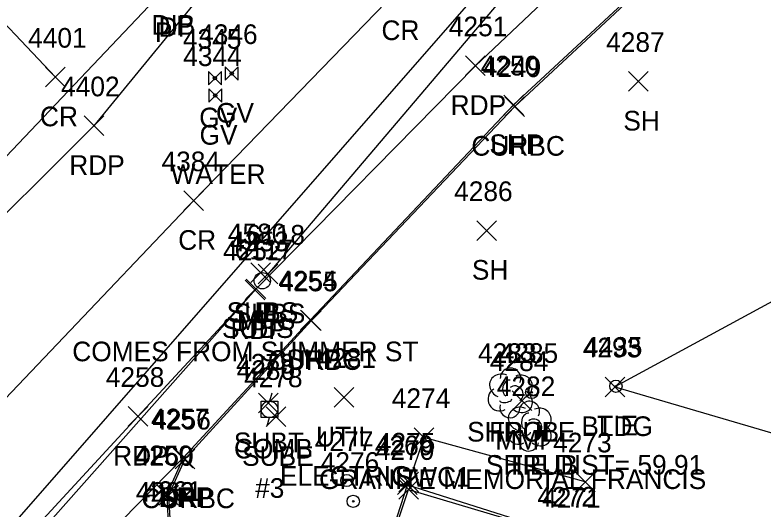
# Model space of a CAD drawing. Extents: x 1653135 to 1655489, y 602711 to 605684.
# Drawn here: x 1653342.1 to 1653418.2, y 604982.6 to 605032.9 of the extents above; entities that cross this region are included whole.
import ezdxf

# ---------------------------------------------------------------- set-up
doc = ezdxf.new("R2010")
doc.units = 0
for name, color, linetype in [('C_A', 7, 'Continuous'), ('C_C', 7, 'Continuous'), ('C_I', 7, 'Continuous'), ('CBP', 7, 'Continuous'), ('D_A', 7, 'Continuous'), ('D_I', 7, 'Continuous'), ('D_TIC', 7, 'Continuous'), ('DCP', 7, 'Continuous'), ('L_A', 7, 'Continuous'), ('L_C', 7, 'Continuous'), ('L_I', 7, 'Continuous'), ('L_TIC', 7, 'Continuous'), ('LBC', 7, 'Continuous'), ('LFP', 7, 'Continuous'), ('LSH', 7, 'Continuous'), ('P_A', 7, 'Continuous'), ('P_I', 7, 'Continuous'), ('P_TIC', 7, 'Continuous'), ('PET', 7, 'Continuous'), ('PRC', 7, 'Continuous'), ('PSP', 7, 'Continuous'), ('R_A', 7, 'Continuous'), ('R_I', 7, 'Continuous'), ('R_TIC', 7, 'Continuous'), ('RC', 7, 'Continuous'), ('RDP', 7, 'Continuous'), ('RSW', 7, 'Continuous'), ('U_A', 7, 'Continuous'), ('U_C', 7, 'Continuous'), ('U_I', 7, 'Continuous'), ('U_TIC', 7, 'Continuous'), ('UDEFAULT', 7, 'Continuous'), ('UP', 7, 'Continuous'), ('UPGW', 7, 'Continuous'), ('USA', 7, 'Continuous'), ('USMH', 7, 'Continuous'), ('UWV', 7, 'Continuous')]:
    doc.layers.add(name, color=color, linetype=linetype)

msp = doc.modelspace()

# ---------------------------------------------------------------- linework, layer by layer
at = {"layer": 'CBP'}
for radius in [0.625, 0.0833]:
    msp.add_circle((1653403.206, 604995.09), radius, dxfattribs=at)
at = {"layer": 'D_TIC'}
for points in [[(1653366.082, 605005.63), (1653368.082, 605007.63)], [(1653368.082, 605005.63), (1653366.082, 605007.63)], [(1653366.8, 605005.5), (1653368.8, 605007.5)], [(1653368.8, 605005.5), (1653366.8, 605007.5)], [(1653365.6, 605004), (1653367.6, 605006)], [(1653367.6, 605004), (1653365.6, 605006)]]:
    msp.add_lwpolyline(points, dxfattribs=at)
at = {"layer": 'DCP'}
for points in [[(1653257.187, 604884.19), (1653422.369, 605073.113)], [(1653334.204, 605011.132), (1653356.94, 605035.103)]]:
    msp.add_lwpolyline(points, dxfattribs=at)
at = {"layer": 'L_TIC'}
for points in [[(1653404.468, 605025.109), (1653406.468, 605027.109)], [(1653406.468, 605025.109), (1653404.468, 605027.109)], [(1653404.468, 605025.109), (1653406.468, 605027.109)], [(1653406.468, 605025.109), (1653404.468, 605027.109)], [(1653389.063, 605009.932), (1653391.063, 605011.932)], [(1653391.063, 605009.932), (1653389.063, 605011.932)], [(1653389.063, 605009.932), (1653391.063, 605011.932)], [(1653391.063, 605009.932), (1653389.063, 605011.932)], [(1653402.096, 604994.024), (1653404.096, 604996.024)], [(1653404.096, 604994.024), (1653402.096, 604996.024)], [(1653402.096, 604994.024), (1653404.096, 604996.024)], [(1653404.096, 604994.024), (1653402.096, 604996.024)], [(1653392.641, 604992.631), (1653394.641, 604994.631)], [(1653394.641, 604992.631), (1653392.641, 604994.631)], [(1653392.641, 604992.631), (1653394.641, 604994.631)], [(1653394.641, 604992.631), (1653392.641, 604994.631)]]:
    msp.add_lwpolyline(points, dxfattribs=at)
at = {"layer": 'LBC'}
msp.add_lwpolyline([(1653550.972, 604997.314), (1653536.605, 605023.768), (1653518.373, 605057.282), (1653491.861, 605043.128), (1653464.288, 605028.284), (1653448.833, 605019.935), (1653427.545, 605008.288), (1653403.096, 604995.024), (1653422.273, 604989.413)], dxfattribs=at)
at = {"layer": 'LFP'}
for radius in [0.625, 0.0833]:
    msp.add_circle((1653394.638, 604994.466), radius, dxfattribs=at)
at = {"layer": 'LSH'}
for p, q in [((1653392.438, 604994.459), (1653392.438, 604994.459)), ((1653392.438, 604994.459), (1653392.438, 604994.459)), ((1653394.345, 604991.082), (1653394.345, 604991.082)), ((1653394.345, 604991.082), (1653394.345, 604991.082))]:
    msp.add_line(p, q, dxfattribs=at)
for centre in [(1653392.485, 604995.893), (1653394.392, 604992.516)]:
    msp.add_arc(centre, 1.047, 335.52715, 180.95627, dxfattribs=at)
for centre, major_axis, ratio, start_param, end_param in [((1653391.646, 604995.126), (1.21, -0.512), 0.895232, 1.570796, 4.712389), ((1653393.479, 604995.043), (-1.141, -0.483), 0.949671, 1.570796, 4.712389), ((1653392.229, 604994.917), (-0.208, -0.792), 0.645439, 3.141593, 6.283185), ((1653392.938, 604994.292), (-0.5, 0.667), 0.989748, 3.141593, 6.283185), ((1653391.355, 604993.751), (0.584, -1.042), 0.959034, 3.141593, 6.283185), ((1653393.438, 604993.626), (-1.09, 0.792), 0.841452, 1.570796, 4.712389), ((1653391.98, 604993.709), (-0.625, -0.083), 0.423636, 0, 3.141593), ((1653392.438, 604992.959), (0.265, 1.061), 0.942809, 1.570796, 4.712389), ((1653393.553, 604991.749), (1.21, -0.512), 0.895232, 1.570796, 4.712389), ((1653395.387, 604991.666), (-1.141, -0.483), 0.949671, 1.570796, 4.712389), ((1653394.137, 604991.541), (-0.208, -0.792), 0.645439, 3.141593, 6.283185), ((1653393.262, 604990.374), (0.584, -1.042), 0.959034, 3.141593, 6.283185), ((1653394.845, 604990.916), (-0.5, 0.667), 0.989748, 3.141593, 6.283185), ((1653395.345, 604990.249), (-1.09, 0.792), 0.841452, 1.570796, 4.712389), ((1653394.345, 604989.582), (0.265, 1.061), 0.942809, 1.570796, 4.712389), ((1653393.887, 604990.332), (-0.625, -0.083), 0.423636, 0, 3.141593)]:
    msp.add_ellipse(centre, major_axis=major_axis, ratio=ratio, start_param=start_param, end_param=end_param, dxfattribs=at)
at = {"layer": 'P_TIC'}
for points in [[(1653387.905, 605026.698), (1653389.905, 605028.698)], [(1653389.905, 605026.698), (1653387.905, 605028.698)], [(1653387.905, 605026.698), (1653389.905, 605028.698)], [(1653389.905, 605026.698), (1653387.905, 605028.698)], [(1653345.194, 605025.541), (1653347.194, 605027.541)], [(1653347.194, 605025.541), (1653345.194, 605027.541)], [(1653345.194, 605025.541), (1653347.194, 605027.541)], [(1653347.194, 605025.541), (1653345.194, 605027.541)], [(1653391.797, 605022.713), (1653393.797, 605024.713)], [(1653393.797, 605022.713), (1653391.797, 605024.713)], [(1653391.797, 605022.713), (1653393.797, 605024.713)], [(1653393.797, 605022.713), (1653391.797, 605024.713)], [(1653349.113, 605020.59), (1653351.113, 605022.59)], [(1653351.113, 605020.59), (1653349.113, 605022.59)], [(1653349.113, 605020.59), (1653351.113, 605022.59)], [(1653351.113, 605020.59), (1653349.113, 605022.59)], [(1653359.25, 605012.969), (1653361.25, 605014.969)], [(1653361.25, 605012.969), (1653359.25, 605014.969)], [(1653359.25, 605012.969), (1653361.25, 605014.969)], [(1653361.25, 605012.969), (1653359.25, 605014.969)], [(1653365.499, 605003.888), (1653367.499, 605005.888)], [(1653367.499, 605003.888), (1653365.499, 605005.888)], [(1653365.499, 605003.888), (1653367.499, 605005.888)], [(1653367.499, 605003.888), (1653365.499, 605005.888)], [(1653371.132, 605000.835), (1653373.132, 605002.835)], [(1653373.132, 605000.835), (1653371.132, 605002.835)], [(1653371.132, 605000.835), (1653373.132, 605002.835)], [(1653373.132, 605000.835), (1653371.132, 605002.835)], [(1653353.584, 604991.023), (1653355.584, 604993.023)], [(1653355.584, 604991.023), (1653353.584, 604993.023)], [(1653353.584, 604991.023), (1653355.584, 604993.023)], [(1653355.584, 604991.023), (1653353.584, 604993.023)], [(1653358.179, 604986.803), (1653360.179, 604988.803)], [(1653360.179, 604986.803), (1653358.179, 604988.803)], [(1653358.179, 604986.803), (1653360.179, 604988.803)], [(1653360.179, 604986.803), (1653358.179, 604988.803)]]:
    msp.add_lwpolyline(points, dxfattribs=at)
at = {"layer": 'PET'}
for points in [[(1653570.485, 605162.786), (1653545.403, 605152.188), (1653524.597, 605144.335), (1653501.66, 605134.239), (1653492.53, 605129.6), (1653483.217, 605126.16), (1653461.507, 605114.196), (1653431.751, 605097.051), (1653402.439, 605074.196), (1653383.496, 605058.488), (1653369.863, 605045.734), (1653350.113, 605021.59), (1653336.009, 605007.549), (1653322.852, 604993.824), (1653302.166, 604970.774), (1653290.93, 604958.375), (1653272.167, 604938.098), (1653250.651, 604913.142), (1653232.406, 604892.896), (1653208.357, 604866.317), (1653177.81, 604831.245), (1653160.535, 604811.983)], [(1653576.316, 605135.262), (1653553.767, 605126.837), (1653519.051, 605112.425), (1653493.535, 605100.339), (1653468.833, 605088.005), (1653447.853, 605075.02), (1653427.596, 605061.865), (1653406.781, 605044.605), (1653388.905, 605027.698), (1653366.499, 605004.888), (1653354.584, 604992.023), (1653334.896, 604970.66), (1653318.046, 604952.193), (1653296.488, 604928.187), (1653274.624, 604903.556), (1653244.239, 604868.756), (1653225.75, 604847.701), (1653206.334, 604825.65), (1653179.645, 604794.747)]]:
    msp.add_lwpolyline(points, dxfattribs=at)
at = {"layer": 'PRC'}
for points in [[(1653576.361, 605149.524), (1653550.317, 605139.021), (1653518.724, 605125.668), (1653498.017, 605116.666), (1653468.035, 605101.489), (1653440.124, 605084.852), (1653411.973, 605063.454), (1653392.179, 605045.924), (1653380.925, 605035.31), (1653360.25, 605013.969), (1653332.49, 604984.793), (1653311.146, 604961.542), (1653300.12, 604949.228), (1653281.614, 604928.677), (1653260.957, 604905.277), (1653242.089, 604884.435), (1653216.566, 604855.116), (1653187.493, 604822.135), (1653170.081, 604802.31)], [(1653325.383, 605048.447), (1653337.388, 605035.857), (1653346.194, 605026.541)]]:
    msp.add_lwpolyline(points, dxfattribs=at)
at = {"layer": 'PSP'}
msp.add_lwpolyline([(1653577.495, 605132.222), (1653555.735, 605120.61), (1653541.776, 605115.966), (1653532.613, 605114.781), (1653532.247, 605110.88), (1653522.733, 605106.898), (1653507.697, 605103.522), (1653493.111, 605096.605), (1653471.403, 605083.027), (1653450.958, 605070.25), (1653430.837, 605057.523), (1653410.321, 605040.006), (1653392.797, 605023.713), (1653372.132, 605001.835), (1653359.179, 604987.803), (1653339.003, 604967.206), (1653322.133, 604948.589), (1653300.744, 604925.192), (1653278.521, 604900.611), (1653247.528, 604865.908), (1653229.566, 604844.432), (1653209.3, 604822.581), (1653182.433, 604791.771)], dxfattribs=at)
at = {"layer": 'R_TIC'}
for points in [[(1653391.919, 605022.548), (1653393.919, 605024.548)], [(1653393.919, 605022.548), (1653391.919, 605024.548)], [(1653391.919, 605022.548), (1653393.919, 605024.548)], [(1653393.919, 605022.548), (1653391.919, 605024.548)], [(1653371.22, 605000.751), (1653373.22, 605002.751)], [(1653373.22, 605000.751), (1653371.22, 605002.751)], [(1653371.22, 605000.751), (1653373.22, 605002.751)], [(1653373.22, 605000.751), (1653371.22, 605002.751)], [(1653382.67, 604988.871), (1653384.67, 604990.871)], [(1653384.67, 604988.871), (1653382.67, 604990.871)], [(1653382.67, 604988.871), (1653384.67, 604990.871)], [(1653384.67, 604988.871), (1653382.67, 604990.871)], [(1653358.179, 604986.803), (1653360.179, 604988.803)], [(1653360.179, 604986.803), (1653358.179, 604988.803)], [(1653358.179, 604986.803), (1653360.179, 604988.803)], [(1653360.179, 604986.803), (1653358.179, 604988.803)], [(1653358.36, 604986.685), (1653360.36, 604988.685)], [(1653360.36, 604986.685), (1653358.36, 604988.685)], [(1653358.36, 604986.685), (1653360.36, 604988.685)], [(1653360.36, 604986.685), (1653358.36, 604988.685)], [(1653380.999, 604984.069), (1653382.999, 604986.069)], [(1653382.999, 604984.069), (1653380.999, 604986.069)], [(1653380.999, 604984.069), (1653382.999, 604986.069)], [(1653382.999, 604984.069), (1653380.999, 604986.069)], [(1653381.14, 604984.345), (1653383.14, 604986.345)], [(1653383.14, 604984.345), (1653381.14, 604986.345)], [(1653381.14, 604984.345), (1653383.14, 604986.345)], [(1653383.14, 604984.345), (1653381.14, 604986.345)], [(1653399.078, 604984.359), (1653401.078, 604986.359)], [(1653401.078, 604984.359), (1653399.078, 604986.359)], [(1653399.078, 604984.359), (1653401.078, 604986.359)], [(1653401.078, 604984.359), (1653399.078, 604986.359)], [(1653381.123, 604983.594), (1653383.123, 604985.594)], [(1653383.123, 604983.594), (1653381.123, 604985.594)], [(1653381.123, 604983.594), (1653383.123, 604985.594)], [(1653383.123, 604983.594), (1653381.123, 604985.594)], [(1653356.514, 604983.058), (1653358.514, 604985.058)], [(1653358.514, 604983.058), (1653356.514, 604985.058)], [(1653356.514, 604983.058), (1653358.514, 604985.058)], [(1653358.514, 604983.058), (1653356.514, 604985.058)], [(1653356.701, 604982.998), (1653358.701, 604984.998)], [(1653358.701, 604982.998), (1653356.701, 604984.998)], [(1653356.701, 604982.998), (1653358.701, 604984.998)], [(1653358.701, 604982.998), (1653356.701, 604984.998)]]:
    msp.add_lwpolyline(points, dxfattribs=at)
at = {"layer": 'RC'}
msp.add_lwpolyline([(1653461.112, 605032.534), (1653449.922, 605049.198), (1653443.907, 605057.821), (1653441.507, 605059.753), (1653437.992, 605060.258), (1653434.799, 605059.429), (1653430.986, 605057.43), (1653410.367, 605039.832), (1653392.919, 605023.548), (1653372.22, 605001.751), (1653359.36, 604987.685), (1653357.701, 604983.998), (1653357.899, 604980.417), (1653359.903, 604976.693), (1653362.858, 604974.486), (1653377.178, 604970.134), (1653381.999, 604985.069), (1653398.467, 604979.845)], dxfattribs=at)
at = {"layer": 'RDP'}
msp.add_lwpolyline([(1653359.179, 604987.803), (1653357.514, 604984.058), (1653357.685, 604980.334), (1653359.785, 604976.668), (1653362.771, 604974.374), (1653377.239, 604970.001), (1653382.123, 604984.594), (1653398.392, 604979.719)], dxfattribs=at)
at = {"layer": 'RSW'}
msp.add_lwpolyline([(1653400.078, 604985.359), (1653383.67, 604989.871), (1653382.14, 604985.345)], dxfattribs=at)
at = {"layer": 'U_TIC'}
for points in [[(1653366.082, 605005.63), (1653368.082, 605007.63)], [(1653368.082, 605005.63), (1653366.082, 605007.63)], [(1653366.8, 605005.5), (1653368.8, 605007.5)], [(1653368.8, 605005.5), (1653366.8, 605007.5)], [(1653365.6, 605004), (1653367.6, 605006)], [(1653367.6, 605004), (1653365.6, 605006)], [(1653366.847, 604992.379), (1653368.847, 604994.379)], [(1653368.847, 604992.379), (1653366.847, 604994.379)], [(1653366.847, 604992.379), (1653368.847, 604994.379)], [(1653368.847, 604992.379), (1653366.847, 604994.379)], [(1653367.644, 604990.99), (1653369.644, 604992.99)], [(1653369.644, 604990.99), (1653367.644, 604992.99)], [(1653367.644, 604990.99), (1653369.644, 604992.99)], [(1653369.644, 604990.99), (1653367.644, 604992.99)]]:
    msp.add_lwpolyline(points, dxfattribs=at)
at = {"layer": 'UDEFAULT'}
for points in [[(1653374.541, 604992.961), (1653376.541, 604994.961)], [(1653376.541, 604992.961), (1653374.541, 604994.961)]]:
    msp.add_lwpolyline(points, dxfattribs=at)
at = {"layer": 'UP'}
for p, q in [((1653368.22, 604994.401), (1653367.97, 604993.568)), ((1653367.137, 604991.901), (1653367.137, 604993.568)), ((1653367.137, 604993.568), (1653368.803, 604993.568)), ((1653368.803, 604993.568), (1653368.803, 604991.901)), ((1653367.97, 604992.734), (1653367.97, 604992.734)), ((1653368.803, 604991.901), (1653367.137, 604991.901)), ((1653367.72, 604991.068), (1653367.97, 604991.901))]:
    msp.add_line(p, q, dxfattribs=at)
msp.add_circle((1653367.97, 604992.734), 0.833, dxfattribs=at)
at = {"layer": 'UPGW'}
for centre, radius in [((1653375.84, 604985.5), 0.625), ((1653375.84, 604985.5), 0.0833), ((1653376.492, 604983.378), 0.625), ((1653376.492, 604983.378), 0.0833)]:
    msp.add_circle(centre, radius, dxfattribs=at)
at = {"layer": 'USA'}
for points in [[(1653424.094, 605072.763), (1653367.8, 605006.5)], [(1653246.475, 604869.474), (1653366.6, 605005)]]:
    msp.add_lwpolyline(points, dxfattribs=at)
at = {"layer": 'USMH'}
for p, q in [((1653367.236, 605005.821), (1653367.236, 605005.821)), ((1653368.069, 605005.821), (1653368.069, 605005.821))]:
    msp.add_line(p, q, dxfattribs=at)
msp.add_circle((1653367.236, 605005.821), 0.833, dxfattribs=at)
at = {"layer": 'UWV'}
for p, q in [((1653361.755, 605027.099), (1653363.088, 605025.766)), ((1653363.088, 605027.099), (1653361.755, 605025.766)), ((1653363.462, 605027.576), (1653364.795, 605026.243)), ((1653364.795, 605027.576), (1653363.462, 605026.243)), ((1653361.788, 605025.335), (1653363.122, 605024.002)), ((1653363.122, 605025.335), (1653361.788, 605024.002))]:
    msp.add_line(p, q, dxfattribs=at)
for points in [[(1653361.755, 605027.099), (1653361.755, 605025.766)], [(1653363.088, 605025.766), (1653363.088, 605027.099)], [(1653363.462, 605027.576), (1653363.462, 605026.243)], [(1653364.795, 605026.243), (1653364.795, 605027.576)], [(1653361.788, 605025.335), (1653361.788, 605024.002)], [(1653363.122, 605024.002), (1653363.122, 605025.335)]]:
    msp.add_lwpolyline(points, dxfattribs=at)
for centre in [(1653364.128, 605026.91), (1653362.422, 605026.433), (1653362.455, 605024.668)]:
    msp.add_circle(centre, 0.167, dxfattribs=at)

# ---------------------------------------------------------------- texts
at = {"layer": 'C_A'}
msp.add_text('TIE', height=2, dxfattribs=at).set_placement((1653401.284, 604990.09))
at = {"layer": 'C_C'}
msp.add_text('TIE DIST= 59.91', height=2, dxfattribs=at).set_placement((1653392.088, 604986.09))
at = {"layer": 'C_I'}
msp.add_text('4435', height=2, dxfattribs=at).set_placement((1653399.946, 604998.09))
at = {"layer": 'D_A'}
for s, p in [('DIB', (1653355.961, 605030.859)), ('DIB', (1653355.961, 605030.859)), ('DI', (1653356.693, 605030.644)), ('P', (1653358.48, 605030.789)), ('P', (1653358.48, 605030.789)), ('P', (1653356.318, 605030.103)), ('P', (1653356.318, 605030.103)), ('P', (1653366.46, 605001.63)), ('P', (1653367.178, 605001.5)), ('P', (1653365.978, 605000))]:
    msp.add_text(s, height=2, dxfattribs=at).set_placement(p)
at = {"layer": 'D_I'}
for s, p in [('4580', (1653363.735, 605009.63)), ('6118', (1653365.627, 605009.5)), ('6117', (1653364.427, 605008))]:
    msp.add_text(s, height=2, dxfattribs=at).set_placement(p)
at = {"layer": 'L_A'}
for s, p in [('SH', (1653403.956, 605021.109)), ('SH', (1653403.956, 605021.109)), ('SH', (1653388.551, 605005.932)), ('SH', (1653388.551, 605005.932)), ('BLDG', (1653399.686, 604990.024)), ('BLDG', (1653399.686, 604990.024)), ('SHRUB', (1653388.068, 604989.459)), ('FPOLE', (1653390.308, 604989.466)), ('MMF', (1653390.925, 604988.631)), ('MMF', (1653390.925, 604988.631)), ('SHRUB', (1653389.975, 604986.082))]:
    msp.add_text(s, height=2, dxfattribs=at).set_placement(p)
at = {"layer": 'L_C'}
msp.add_text('GRANITE MEMORIAL FRANCIS', height=2, dxfattribs=at).set_placement((1653373.012, 604984.631))
msp.add_text('GRANITE MEMORIAL FRANCIS', height=2, dxfattribs=at).set_placement((1653373.012, 604984.631))
at = {"layer": 'L_I'}
for s, p in [('4287', (1653402.208, 605029.109)), ('4287', (1653402.208, 605029.109)), ('4286', (1653386.748, 605013.932)), ('4286', (1653386.748, 605013.932)), ('4293', (1653399.836, 604998.024)), ('4293', (1653399.836, 604998.024)), ('4283', (1653389.178, 604997.459)), ('4285', (1653391.379, 604997.466)), ('4284', (1653390.382, 604996.631)), ('4284', (1653390.382, 604996.631)), ('4282', (1653391.085, 604994.082))]:
    msp.add_text(s, height=2, dxfattribs=at).set_placement(p)
at = {"layer": 'P_A'}
for s, p in [('CR', (1653379.358, 605030.31)), ('CR', (1653379.358, 605030.31)), ('RDP', (1653386.393, 605022.698)), ('RDP', (1653386.393, 605022.698)), ('CR', (1653344.627, 605021.541)), ('CR', (1653344.627, 605021.541)), ('SHP', (1653390.333, 605018.713)), ('SHP', (1653390.333, 605018.713)), ('RDP', (1653347.601, 605016.59)), ('RDP', (1653347.601, 605016.59)), ('CR', (1653358.683, 605008.969)), ('CR', (1653358.683, 605008.969)), ('RDP', (1653363.987, 604999.888)), ('RDP', (1653363.987, 604999.888)), ('SHP', (1653369.667, 604996.835)), ('SHP', (1653369.667, 604996.835)), ('RDP', (1653352.072, 604987.023)), ('RDP', (1653352.072, 604987.023)), ('SHP', (1653356.715, 604982.803)), ('SHP', (1653356.715, 604982.803))]:
    msp.add_text(s, height=2, dxfattribs=at).set_placement(p)
at = {"layer": 'P_I'}
for s, p in [('4251', (1653386.212, 605030.698)), ('4251', (1653386.212, 605030.698)), ('4401', (1653343.422, 605029.541)), ('4401', (1653343.422, 605029.541)), ('4250', (1653389.451, 605026.713)), ('4250', (1653389.451, 605026.713)), ('4402', (1653346.774, 605024.59)), ('4402', (1653346.774, 605024.59)), ('4384', (1653356.99, 605016.969)), ('4384', (1653356.99, 605016.969)), ('4252', (1653363.239, 605007.888)), ('4252', (1653363.239, 605007.888)), ('4254', (1653368.872, 605004.835)), ('4254', (1653368.872, 605004.835)), ('4258', (1653351.324, 604995.023)), ('4258', (1653351.324, 604995.023)), ('4257', (1653355.92, 604990.803)), ('4257', (1653355.92, 604990.803))]:
    msp.add_text(s, height=2, dxfattribs=at).set_placement(p)
at = {"layer": 'R_A'}
for s, p in [('CURBC', (1653388.502, 605018.548)), ('CURBC', (1653388.502, 605018.548)), ('CURBC', (1653367.802, 604996.751)), ('CURBC', (1653367.802, 604996.751)), ('SWC1', (1653380.709, 604984.871)), ('SWC1', (1653380.709, 604984.871)), ('CURBC', (1653354.943, 604982.685)), ('CURBC', (1653354.943, 604982.685)), ('DRP', (1653356.668, 604982.803)), ('DRP', (1653356.668, 604982.803))]:
    msp.add_text(s, height=2, dxfattribs=at).set_placement(p)
at = {"layer": 'R_I'}
for s, p in [('4249', (1653389.652, 605026.548)), ('4249', (1653389.652, 605026.548)), ('4255', (1653368.96, 605004.751)), ('4255', (1653368.96, 605004.751)), ('4274', (1653380.41, 604992.871)), ('4274', (1653380.41, 604992.871)), ('4257', (1653355.92, 604990.803)), ('4257', (1653355.92, 604990.803)), ('4256', (1653356.045, 604990.685)), ('4256', (1653356.045, 604990.685)), ('4269', (1653378.684, 604988.069)), ('4269', (1653378.684, 604988.069)), ('4275', (1653378.881, 604988.345)), ('4275', (1653378.881, 604988.345)), ('4273', (1653396.819, 604988.359)), ('4273', (1653396.819, 604988.359)), ('4259', (1653354.246, 604987.058)), ('4259', (1653354.246, 604987.058)), ('4260', (1653354.308, 604986.998)), ('4260', (1653354.308, 604986.998)), ('4270', (1653378.777, 604987.594)), ('4270', (1653378.777, 604987.594)), ('4262', (1653354.378, 604983.334)), ('4262', (1653354.378, 604983.334)), ('4261', (1653355.159, 604983.417)), ('4261', (1653355.159, 604983.417)), ('4272', (1653395.207, 604982.845)), ('4272', (1653395.207, 604982.845)), ('4271', (1653395.699, 604982.719)), ('4271', (1653395.699, 604982.719))]:
    msp.add_text(s, height=2, dxfattribs=at).set_placement(p)
at = {"layer": 'U_A'}
for s, p in [('GV', (1653360.823, 605021.433)), ('GV', (1653362.53, 605021.91)), ('GV', (1653360.857, 605019.668)), ('SUBS', (1653363.617, 605001.63)), ('SUBS', (1653364.335, 605001.5)), ('MHS', (1653364.653, 605000.821)), ('SUBS', (1653363.135, 605000)), ('UTIL', (1653372.706, 604988.961)), ('SUBT', (1653364.343, 604988.379)), ('SUBT', (1653364.343, 604988.379)), ('COMB', (1653364.356, 604987.734)), ('SUBE', (1653365.18, 604986.99)), ('SUBE', (1653365.18, 604986.99))]:
    msp.add_text(s, height=2, dxfattribs=at).set_placement(p)
at = {"layer": 'U_C'}
for s, p in [('WATER', (1653357.912, 605015.668)), ('COMES FROM SUMMER ST', (1653347.909, 604997.63)), ('ELECTRIC', (1653369.029, 604984.961)), ('#3', (1653366.505, 604983.734))]:
    msp.add_text(s, height=2, dxfattribs=at).set_placement(p)
at = {"layer": 'U_I'}
for s, p in [('4346', (1653360.814, 605029.91)), ('4345', (1653359.162, 605029.433)), ('4344', (1653359.195, 605027.668)), ('4580', (1653363.735, 605009.63)), ('6118', (1653365.627, 605009.5)), ('4253', (1653363.976, 605008.821)), ('6117', (1653364.427, 605008)), ('4281', (1653372.848, 604996.961)), ('4279', (1653364.579, 604996.379)), ('4279', (1653364.579, 604996.379)), ('4280', (1653364.624, 604995.734)), ('4278', (1653365.385, 604994.99)), ('4278', (1653365.385, 604994.99)), ('4277', (1653372.58, 604988.5)), ('4276', (1653373.177, 604986.378))]:
    msp.add_text(s, height=2, dxfattribs=at).set_placement(p)

doc.saveas('drawing.dxf')
